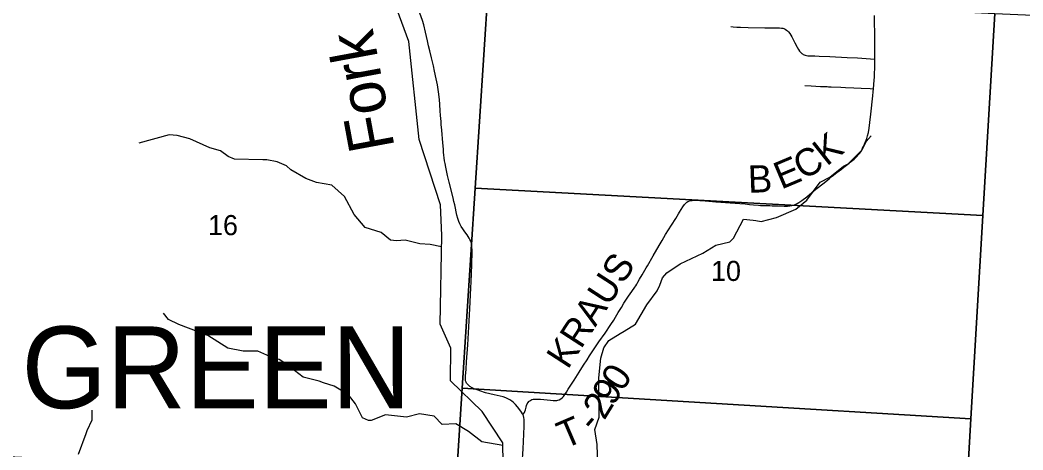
# Model space of a CAD drawing. Extents: x 0 to 34, y 0 to 22.
# Drawn here: x 3.179 to 5.267, y 19.148 to 20.043 of the extents above; entities that cross this region are included whole.
import ezdxf

# ---------------------------------------------------------------- set-up
doc = ezdxf.new("R2010")
doc.units = 0
for name, color, linetype in [('GM_X_County_Road', 7, 'Continuous'), ('GM_X_Minor_River', 7, 'Continuous'), ('GM_X_Minor_River_Text', 7, 'Continuous'), ('GM_X_Section', 7, 'Continuous'), ('GM_X_Section_Text', 7, 'Continuous'), ('GM_X_Township_Road', 7, 'Continuous'), ('GM_X_Township_Road_Text', 7, 'Continuous'), ('GM_X_Township_Text', 7, 'Continuous')]:
    doc.layers.add(name, color=color, linetype=linetype)

msp = doc.modelspace()

# ---------------------------------------------------------------- linework, layer by layer
at = {"layer": 'GM_X_County_Road'}
for points in [[(4.2012, 19.2503), (4.1987, 19.252), (4.1948, 19.2541), (4.1902, 19.2561), (4.1848, 19.258), (4.1787, 19.2596), (4.166, 19.2624), (4.1571, 19.2645), (4.1483, 19.2668), (4.1362, 19.2706), (4.1327, 19.2718), (4.1264, 19.2742), (4.1231, 19.2758), (4.1202, 19.2772), (4.1157, 19.2799), (4.1127, 19.2822), (4.1105, 19.2844), (4.1087, 19.2867), (4.1076, 19.2887), (4.1068, 19.2913), (4.1064, 19.2961), (4.1064, 19.301), (4.1077, 19.3158), (4.1088, 19.3313), (4.1112, 19.3667), (4.1153, 19.4411), (4.1173, 19.4852), (4.118, 19.4976), (4.1195, 19.533), (4.1203, 19.5616), (4.12, 19.572), (4.1197, 19.5748), (4.1191, 19.5775), (4.1181, 19.5802), (4.1173, 19.5822), (4.1156, 19.5855), (4.114, 19.5885), (4.11, 19.5951), (4.1052, 19.6017), (4.1008, 19.6077), (4.0974, 19.6128), (4.0946, 19.6182), (4.0925, 19.6233), (4.0906, 19.6292), (4.0887, 19.6363), (4.0841, 19.6576), (4.0825, 19.6649), (4.0806, 19.6727), (4.0724, 19.7053), (4.069, 19.7191), (4.0653, 19.7361), (4.0639, 19.744), (4.0631, 19.7495), (4.061, 19.7673), (4.0605, 19.7741), (4.0594, 19.7871), (4.0573, 19.8131), (4.0562, 19.8254), (4.0557, 19.8315), (4.0546, 19.8441), (4.054, 19.8539), (4.0531, 19.8669), (4.0521, 19.8775), (4.0502, 19.8935), (4.0481, 19.9077), (4.0457, 19.9205), (4.0421, 19.9363), (4.0396, 19.9472), (4.0355, 19.9641), (4.0321, 19.9786), (4.0297, 19.9889), (4.0274, 19.9992), (4.0232, 20.0173), (4.0195, 20.0324), (4.0169, 20.0414), (4.0117, 20.0567)], [(4.2248, 19.1182), (4.2263, 19.1499), (4.2278, 19.1803), (4.2287, 19.197), (4.229, 19.2051), (4.2288, 19.2108), (4.2281, 19.2152), (4.227, 19.2189), (4.2258, 19.2215), (4.2254, 19.2224), (4.2232, 19.2263), (4.22, 19.2309), (4.2149, 19.2373), (4.2104, 19.2424), (4.2063, 19.2464), (4.2029, 19.2492), (4.2012, 19.2503)]]:
    msp.add_lwpolyline(points, dxfattribs=at)
at = {"layer": 'GM_X_Minor_River'}
for points in [[(4.1907, 18.8574), (4.1719, 18.9702), (4.1862, 19.0352), (4.1845, 19.1623), (4.1415, 19.2276), (4.075, 19.2911), (4.0757, 19.3594), (4.0541, 19.4097), (4.057, 19.5938), (4.0546, 19.6579), (4.0103, 19.7941), (3.9887, 19.9981), (3.9324, 20.1513), (3.8898, 20.2086), (3.6983, 20.2805), (3.6841, 20.2933), (3.6464, 20.3317), (3.5061, 20.3456), (3.3197, 20.2301), (3.2986, 20.2204)], [(4.0566, 19.5703), (4.0329, 19.5754), (4.0117, 19.5769), (3.9806, 19.5841), (3.9628, 19.583), (3.9503, 19.5845), (3.9306, 19.6004), (3.8976, 19.611), (3.8745, 19.6376), (3.8544, 19.6756), (3.8279, 19.6988), (3.7964, 19.7041), (3.774, 19.7124), (3.743, 19.7306), (3.7339, 19.739), (3.7145, 19.7477), (3.6925, 19.7518), (3.6842, 19.7518), (3.6258, 19.7529), (3.6122, 19.7586), (3.5963, 19.7704), (3.5739, 19.7768), (3.5322, 19.7954), (3.5064, 19.8022), (3.4894, 19.8037), (3.4261, 19.7865)], [(4.3826, 19.0946), (4.3804, 19.1588), (4.3762, 19.19), (4.3849, 19.2158), (4.3842, 19.2976), (4.3884, 19.3386), (4.3948, 19.3599), (4.4047, 19.3755), (4.4286, 19.39), (4.4373, 19.3949), (4.4608, 19.4094), (4.4839, 19.4497), (4.5059, 19.479), (4.5109, 19.4908), (4.5166, 19.5056), (4.526, 19.5163), (4.5537, 19.5349), (4.6007, 19.5574), (4.6277, 19.5742), (4.6569, 19.5811), (4.6648, 19.5883), (4.6857, 19.6282), (4.7058, 19.626), (4.7111, 19.6256), (4.7221, 19.6233), (4.7539, 19.6313), (4.7945, 19.6492), (4.8176, 19.6679), (4.8453, 19.7052), (4.8654, 19.7158), (4.8934, 19.7387), (4.9037, 19.7432), (4.9325, 19.7722), (4.9412, 19.7897), (4.9515, 19.8015)], [(4.1846, 19.157), (4.1404, 19.1643), (4.1131, 19.1859), (4.0866, 19.2022), (4.0582, 19.2007), (4.0411, 19.2177), (4.0104, 19.223), (3.9835, 19.2158), (3.9399, 19.2203), (3.9103, 19.2089), (3.9043, 19.2085), (3.8918, 19.2145), (3.8774, 19.2434), (3.863, 19.262), (3.833, 19.2806), (3.8107, 19.2874), (3.8016, 19.2909), (3.7682, 19.2992), (3.7326, 19.3269), (3.7182, 19.336), (3.7053, 19.3394), (3.6742, 19.3534), (3.6435, 19.3534), (3.6113, 19.3598), (3.57, 19.386), (3.5097, 19.4084), (3.4877, 19.4194), (3.4775, 19.4323)], [(3.3008, 19.1386), (3.3167, 19.182), (3.3186, 19.1877), (3.3292, 19.2101), (3.3292, 19.2307)]]:
    msp.add_lwpolyline(points, dxfattribs=at)
at = {"layer": 'GM_X_Section'}
for points in [[(3.1221, 20.1708), (4.1536, 20.1097), (4.1266, 19.6923), (4.0998, 19.2759), (4.0875, 19.0909), (4.0872, 19.0874), (3.4908, 19.1174), (3.0501, 19.1382), (3.0637, 19.3317), (3.093, 19.7459)], [(4.1536, 20.1097), (5.2086, 20.056), (5.1842, 19.6356), (4.1266, 19.6923)], [(6.2522, 20.0112), (6.1895, 18.9865), (5.1485, 19.0298), (5.159, 19.2125), (5.1842, 19.6356), (5.2086, 20.056)], [(5.1842, 19.6356), (5.159, 19.2125), (4.0998, 19.2759), (4.1266, 19.6923)], [(4.0998, 19.2759), (5.159, 19.2125), (5.1485, 19.0298), (4.0875, 19.0909)]]:
    msp.add_lwpolyline(points, close=True, dxfattribs=at)
at = {"layer": 'GM_X_Township_Road'}
for points in [[(4.9052, 19.7449), (4.9075, 19.7468), (4.9158, 19.7533), (4.9181, 19.7553), (4.9217, 19.7589), (4.9246, 19.7619), (4.9278, 19.7657), (4.931, 19.7704), (4.9334, 19.7756), (4.9353, 19.7795), (4.9387, 19.7878), (4.942, 19.796), (4.9438, 19.8017), (4.9455, 19.8083), (4.9471, 19.8174), (4.9488, 19.8291), (4.9508, 19.8469), (4.9547, 19.8846), (4.9557, 19.8932), (4.9562, 19.8994), (4.9571, 19.9087), (4.9579, 19.9172), (4.9583, 19.9234), (4.9585, 19.9302), (4.9587, 19.9438), (4.959, 19.9613), (4.9592, 19.9798), (4.9592, 19.9972), (4.9588, 20.0165), (4.9584, 20.0364), (4.9584, 20.0519)], [(4.6591, 20.0293), (4.6641, 20.0287), (4.6715, 20.0281), (4.6789, 20.0277), (4.6955, 20.0271), (4.7297, 20.0267), (4.7407, 20.0267), (4.7605, 20.0265), (4.7647, 20.026), (4.7671, 20.0255), (4.7693, 20.0249), (4.7708, 20.0241), (4.7722, 20.0234), (4.7748, 20.0219), (4.7772, 20.02), (4.7793, 20.0178), (4.7819, 20.0144), (4.7841, 20.0111), (4.7862, 20.0077), (4.7882, 20.0039), (4.7924, 19.995), (4.7969, 19.986), (4.7997, 19.9811), (4.8019, 19.978), (4.8039, 19.9756), (4.8068, 19.9731), (4.8083, 19.9721), (4.81, 19.9711), (4.8118, 19.9704), (4.8136, 19.9697), (4.8166, 19.969), (4.8197, 19.9685), (4.824, 19.9682), (4.834, 19.9679), (4.8433, 19.9675), (4.865, 19.9665), (4.9015, 19.9649), (4.9226, 19.9639), (4.959, 19.9613)], [(4.8135, 19.9061), (4.8266, 19.9055), (4.8457, 19.9046), (4.8531, 19.9042), (4.8568, 19.9041), (4.8599, 19.904), (4.8623, 19.9039), (4.8679, 19.9038), (4.8883, 19.9032), (4.8982, 19.9025), (4.9149, 19.9017), (4.9304, 19.9009), (4.949, 19.8999), (4.9562, 19.8994)], [(4.7366, 19.6563), (4.7405, 19.6562), (4.7455, 19.6561), (4.7505, 19.6561), (4.7543, 19.656), (4.7573, 19.6558), (4.7703, 19.6551), (4.7771, 19.6551), (4.782, 19.6555), (4.7863, 19.6562), (4.7904, 19.6574), (4.7943, 19.659), (4.7971, 19.6604), (4.8007, 19.6627), (4.8067, 19.6671), (4.8171, 19.6749), (4.8229, 19.6796), (4.8324, 19.6876), (4.8387, 19.6927), (4.8504, 19.7019), (4.8636, 19.7123), (4.8699, 19.7173), (4.8796, 19.7249), (4.8895, 19.7325), (4.8944, 19.7363), (4.9052, 19.7449)], [(4.2389, 19.2488), (4.2402, 19.2499), (4.2423, 19.2513), (4.2445, 19.2524), (4.2476, 19.2532), (4.2507, 19.2536), (4.2544, 19.2536), (4.2625, 19.2531), (4.2834, 19.2509), (4.2888, 19.2503), (4.2932, 19.2503), (4.2964, 19.2504), (4.2991, 19.251), (4.3014, 19.2517), (4.3051, 19.2537), (4.3077, 19.2559), (4.3105, 19.2588), (4.3135, 19.2627), (4.317, 19.2681), (4.3206, 19.2743), (4.3246, 19.2806), (4.3328, 19.2931), (4.3435, 19.3098), (4.3525, 19.324), (4.3598, 19.3355), (4.3648, 19.3434), (4.3716, 19.3537), (4.3844, 19.3726), (4.3972, 19.391), (4.4091, 19.4084), (4.4152, 19.4178), (4.4191, 19.4241), (4.4248, 19.4337), (4.4311, 19.4444), (4.4366, 19.4535), (4.4402, 19.4593), (4.4461, 19.468), (4.453, 19.4776), (4.4594, 19.4865), (4.461, 19.4891), (4.4631, 19.4928), (4.4654, 19.497), (4.4691, 19.5034), (4.4742, 19.5119), (4.4831, 19.5269), (4.4855, 19.5312), (4.4973, 19.5516), (4.5097, 19.5731), (4.516, 19.5838), (4.5233, 19.5961), (4.5355, 19.6154), (4.5443, 19.6296), (4.5501, 19.6391), (4.552, 19.6423), (4.5556, 19.6481), (4.5592, 19.6539), (4.5625, 19.6584), (4.5646, 19.6608), (4.5675, 19.6632), (4.5696, 19.6646), (4.5719, 19.6656), (4.5748, 19.6666), (4.5784, 19.6672), (4.5829, 19.6675), (4.588, 19.6673), (4.5946, 19.6667), (4.6059, 19.666), (4.6212, 19.6649), (4.6279, 19.6645), (4.6477, 19.6631), (4.6775, 19.6608), (4.6886, 19.6597), (4.6982, 19.6588), (4.7066, 19.6579), (4.717, 19.6571), (4.7207, 19.6567), (4.7256, 19.6566), (4.7366, 19.6563)], [(4.2258, 19.2215), (4.2274, 19.2229), (4.2294, 19.2255), (4.2301, 19.2273), (4.2313, 19.2312), (4.2326, 19.2365), (4.2336, 19.2401), (4.2351, 19.2436), (4.2367, 19.2463), (4.2383, 19.2482), (4.2389, 19.2488)]]:
    msp.add_lwpolyline(points, dxfattribs=at)

# ---------------------------------------------------------------- texts
at = {"layer": 'GM_X_Minor_River_Text'}
msp.add_text('Fork', height=0.09468, rotation=100.5169, dxfattribs=at).set_placement((3.9593, 19.7774))
at = {"layer": 'GM_X_Section_Text'}
for s, p in [('16', (3.5704, 19.5948)), ('10', (4.6179, 19.4994))]:
    msp.add_text(s, height=0.04186, rotation=0, dxfattribs=at).set_placement(p)
at = {"layer": 'GM_X_Township_Road_Text'}
for s, height, rotation, p in [('K', 0.0568, 38.4708, (4.8586, 19.737)), ('E', 0.0568, 22.8819, (4.7641, 19.6893)), ('C', 0.0568, 28.8789, (4.8091, 19.7087)), ('B', 0.0568, 2.069, (4.6956, 19.6828)), ('KRAUS', 0.05682, 57.0662, (4.3195, 19.3135)), ('0', 0.0568, 56.9277, (4.4328, 19.2667)), ('9', 0.0568, 57.0734, (4.4138, 19.2373)), ('2', 0.0568, 58.3651, (4.3956, 19.2078)), ('T', 0.0568, 23.1688, (4.3128, 19.1491)), ('-', 0.0568, 48.5922, (4.3739, 19.1818))]:
    msp.add_text(s, height=height, rotation=rotation, dxfattribs=at).set_placement(p)
at = {"layer": 'GM_X_Township_Text'}
msp.add_text('GREEN', height=0.17045, rotation=0, dxfattribs=at).set_placement((3.1821, 19.2343))

doc.saveas('drawing.dxf')
